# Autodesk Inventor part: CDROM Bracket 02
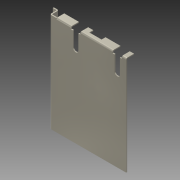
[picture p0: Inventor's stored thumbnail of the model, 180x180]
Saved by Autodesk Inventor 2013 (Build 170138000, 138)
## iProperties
Created: 2005-12
Material: Allgemein
Document SubType Name: Sheet Metal
Mass: 8.77235 g
Surface Area: 180.456 cm^2
Volume: 8.77235 cm^3
Density: 1 g/cm^3
Sheet Metal Rule: 1.0 mm
Author: Autodesk, Inc.
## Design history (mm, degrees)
node "Contour Flange1"
  sketch "Sketch2"
    geometry: L1 (11, 25)-(16, 25); L2 (16, 25)-(16, 18); L3 (16, 18)-(92, 18)
    constraints: 6 end point, 1 parallel
    dimensions: "d1" = 90 deg angle of L2 L1; "d2" = 5 distance of L1.start L1.end; "d3" = 7 distance between parallel lines of L3 L1; "d22" = 81 horizontal distance of L3.end L1.start (computed from OPTIC_SLOT_)
node "Flange3"
sketch "Sketch5"
  geometry: L1 (15, -8)-(15, -2) reference; L2 (24, -2)-(24, -8) reference; L3 (14.8, 1.322)-(24.2, 1.322); L4 (24.2, 1.322)-(24.2, -8.678); L5 (24.2, -8.678)-(14.8, -8.678); L6 (14.8, -8.678)-(14.8, 1.322); L7 (16.8, -8.678)-(22.2, -8.678); L8 (22.2, -8.678)-(22.2, -23.678); L9 (22.2, -23.678)-(16.8, -23.678); L10 (16.8, -23.678)-(16.8, -8.678); 1 further point
  constraints: 20 end point, 4 parallel, 2 horizontal, 2 perpendicular, 2 vertical, 1 horizontal alignment, 1 midpoint, 1 point on line, 6 other
  dimensions: "d33" = 0.2 distance between parallel lines of L6 L1 (derived); "d34" = 0.2 distance between parallel lines of L4 L2 (derived); "d35" = 9.4 distance of L3.start L3.end; "d38" = 2 distance between parallel lines of L4 L8; "d39" = 2 distance between parallel lines of L10 L6 (= d38); "d40" = 15 distance between parallel lines of L9 L7; "d41" = 10 distance of L3.end L4.end
cut "Cut1" sketch "Sketch5" dims "d42" = 1 (= Thickness), "d43" = 0
sketch "Sketch6"
  geometry: L1 (-41.2, 6.5)-(-28.8, 6.5); L2 (-28.8, 6.5)-(-28.8, 2.5); L3 (-28.8, 2.5)-(-41.2, 2.5); L4 (-41.2, 2.5)-(-41.2, 6.5); L5 (-46.3, 6.5)-(-46.3, 0) reference
  constraints: 8 end point, 2 parallel, 1 horizontal, 1 perpendicular
  dimensions: "d49" = 4 distance of L1.end L2.end; "d62" = 5.1 distance between parallel lines of L5 L4; "d63" = 12.4 distance of L1.start L1.end
cut "Cut2" sketch "Sketch6" dims "d51" = 1 (= Thickness), "d52" = 0
pattern_linear "Rectangular Pattern2" dims "d66" = 42
body "Solid1"
face "Plate1" dims "d8" = 100, "d11" = 2 (= MinimumRemnant), "d13" = 0.5 (= BendRadius), "d14" = 1, "SeamGap" = 0.01, "Thickness" = 1
bend "Bend1" dims "d9" = 1 (= BendReliefWidth), "d10" = 0.5 (= BendReliefDepth), "d11" = 2 (= MinimumRemnant), "d12" = 0.5 (= BendRadius), "d13" = 0.5 (= BendRadius), "d14" = 1, "SeamGap" = 0.01, "Thickness" = 1
sketch "Sketch7"
  geometry: L1 (-5, 0)-(-75.5, 0); L2 (-75.5, 0)-(-75.5, 8); L3 (-75.5, 8)-(-5, 8); L4 (-5, 8)-(-5, 0)
  constraints: 8 end point
face "Plate4" dims "d53" = 0, "d54" = 5, "d57" = 2 (= MinimumRemnant), "d59" = 8, "d60" = 90 deg, "d61" = 0.5 (= BendRadius), "SeamGap" = 0.01, "Thickness" = 1
bend "Bend4" dims "d55" = 1 (= BendReliefWidth), "d56" = 0.5 (= BendReliefDepth), "d57" = 2 (= MinimumRemnant), "d58" = 0.5 (= BendRadius), "d59" = 8, "d60" = 90 deg, "d61" = 0.5 (= BendRadius), "SeamGap" = 0.01, "Thickness" = 1
other parameters: "BendRadius" = 0.5, "BendReliefWidth" = 1 (= Thickness), "BendReliefDepth" = 0.5 (= 0.5 x Thickness), "CornerReliefSize" = 4 (= 4 x Thickness), "MinimumRemnant" = 2 (= 2 x Thickness), "TransitionRadius" = 0.5 (= BendRadius), "JacobiRadiusSize" = 1 (= Thickness), "GapSize" = 1 (= Thickness)
